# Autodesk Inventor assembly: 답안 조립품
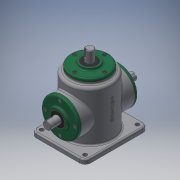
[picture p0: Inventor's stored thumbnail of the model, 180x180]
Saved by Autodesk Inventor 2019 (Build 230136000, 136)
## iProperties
Created: 2020-12
Part Number: 답안 조립품
Material: 일반
Document SubType Name: Assembly
Designer: jun-1-14
Author: jun-1-14
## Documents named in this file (16)
- C:\Users\jun-1-14\Desktop\701207V1005\답안 조립품.iam
- C:\Users\jun-1-14\Desktop\701207V1005\본체.ipt
- C:\Users\jun-1-14\Desktop\701207V1005\메인 베벨기어.ipt
- C:\Users\jun-1-14\Desktop\701207V1005\메인 축.ipt
- 메인 축.ipt
- C:\Users\jun-1-14\Desktop\701207V1005\베어링 6203.ipt
- C:\Users\jun-1-14\Desktop\701207V1005\볼트 M4.ipt
- 볼트 M4.ipt
- C:\Users\jun-1-14\Desktop\701207V1005\서브 베벨기어.ipt
- C:\Users\jun-1-14\Desktop\701207V1005\서브 축.ipt
- 서브 축.ipt
- C:\Users\jun-1-14\Desktop\701207V1005\오일 실.ipt
- 오일 실.ipt
- C:\Users\jun-1-14\Desktop\701207V1005\커버.ipt
- C:\Users\jun-1-14\Desktop\701207V1005\키 4x4.ipt
- C:\Users\jun-1-14\Desktop\701207V1005\키 5x5.ipt
